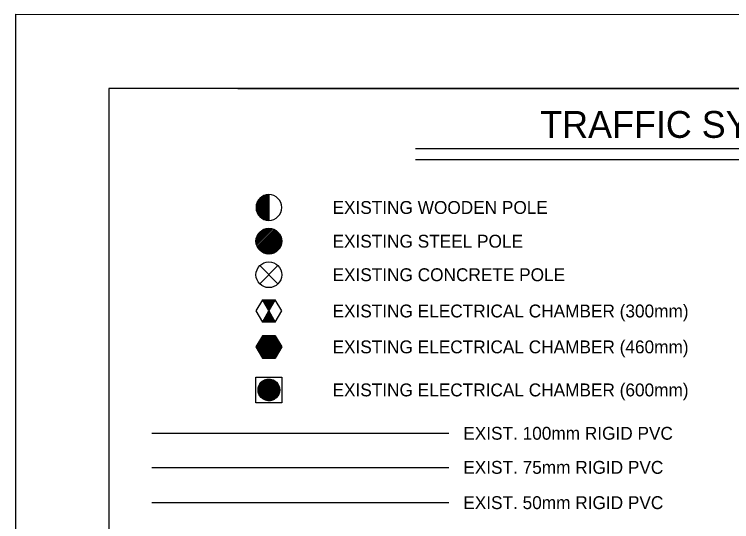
# Model space of a CAD drawing. Extents: x 595568 to 603392, y 4837996 to 4846579.
# Drawn here: x 603056.6 to 603080.76, y 4846519.3 to 4846536.38 of the extents above; entities that cross this region are included whole.
import ezdxf

# ---------------------------------------------------------------- set-up
doc = ezdxf.new("R2010")
doc.units = 0
for name, color, linetype in [('-PRINT HALFSIZE', 7, 'Continuous'), ('ENG_BORDER', 7, 'Continuous'), ('TCS_100mm-EXIST', 7, 'Continuous'), ('TCS_50mm-EXIST', 7, 'Continuous'), ('TCS_75mm-EXIST', 7, 'Continuous'), ('TCS_ELEC-CHAMBER-EXIST', 7, 'Continuous'), ('TCS_LEGEND', 7, 'Continuous'), ('TCS_POLE-EXIST', 7, 'Continuous')]:
    doc.layers.add(name, color=color, linetype=linetype)

msp = doc.modelspace()

# ---------------------------------------------------------------- linework, layer by layer
at = {"layer": '-PRINT HALFSIZE'}
msp.add_lwpolyline([(603056.659, 4846536.385), (603261.877, 4846536.304), (603261.821, 4846396.201), (603056.604, 4846396.282)], close=True, dxfattribs=at)
at = {"layer": 'ENG_BORDER'}
for points in [[(603258.618, 4846533.885), (603059.791, 4846533.885)], [(603059.791, 4846533.885), (603059.791, 4846399.391)]]:
    msp.add_lwpolyline(points, dxfattribs=at)
at = {"layer": 'TCS_100mm-EXIST'}
msp.add_line((603061.232, 4846522.272), (603071.232, 4846522.272), dxfattribs=at)
at = {"layer": 'TCS_50mm-EXIST'}
msp.add_line((603061.232, 4846519.936), (603071.232, 4846519.936), dxfattribs=at)
at = {"layer": 'TCS_75mm-EXIST'}
msp.add_line((603061.232, 4846521.124), (603071.232, 4846521.124), dxfattribs=at)
at = {"layer": 'TCS_ELEC-CHAMBER-EXIST'}
for p, q in [((603064.963, 4846526.758), (603064.972, 4846526.767)), ((603064.971, 4846526.745), (603064.993, 4846526.767)), ((603064.978, 4846526.732), (603065.013, 4846526.767)), ((603064.986, 4846526.719), (603065.033, 4846526.767)), ((603064.993, 4846526.706), (603065.054, 4846526.767)), ((603065.001, 4846526.693), (603065.074, 4846526.767)), ((603065.008, 4846526.68), (603065.095, 4846526.767)), ((603065.016, 4846526.668), (603065.115, 4846526.767)), ((603065.023, 4846526.655), (603065.136, 4846526.767)), ((603065.031, 4846526.642), (603065.156, 4846526.767)), ((603065.038, 4846526.629), (603065.177, 4846526.767)), ((603065.045, 4846526.616), (603065.197, 4846526.767)), ((603065.053, 4846526.603), (603065.217, 4846526.767)), ((603065.06, 4846526.59), (603065.238, 4846526.767)), ((603065.068, 4846526.577), (603065.258, 4846526.767)), ((603065.075, 4846526.564), (603065.279, 4846526.767)), ((603065.083, 4846526.551), (603065.299, 4846526.767)), ((603065.09, 4846526.538), (603065.32, 4846526.767)), ((603065.098, 4846526.525), (603065.34, 4846526.767)), ((603065.105, 4846526.512), (603065.361, 4846526.767)), ((603065.113, 4846526.499), (603065.381, 4846526.767)), ((603065.12, 4846526.486), (603065.378, 4846526.744)), ((603065.128, 4846526.473), (603065.35, 4846526.696)), ((603065.135, 4846526.46), (603065.323, 4846526.647)), ((603065.143, 4846526.447), (603065.295, 4846526.599)), ((603065.15, 4846526.434), (603065.267, 4846526.551)), ((603065.158, 4846526.421), (603065.239, 4846526.502)), ((603064.961, 4846526.016), (603065.234, 4846526.289)), ((603064.981, 4846526.016), (603065.242, 4846526.276)), ((603064.982, 4846526.057), (603065.227, 4846526.302)), ((603065.002, 4846526.016), (603065.249, 4846526.263)), ((603065.01, 4846526.106), (603065.219, 4846526.315)), ((603065.022, 4846526.016), (603065.257, 4846526.25)), ((603065.038, 4846526.154), (603065.212, 4846526.328)), ((603065.043, 4846526.016), (603065.264, 4846526.237)), ((603065.063, 4846526.016), (603065.271, 4846526.224)), ((603065.066, 4846526.202), (603065.204, 4846526.341)), ((603065.094, 4846526.251), (603065.197, 4846526.354)), ((603065.122, 4846526.299), (603065.189, 4846526.367)), ((603065.149, 4846526.348), (603065.182, 4846526.38)), ((603065.165, 4846526.408), (603065.211, 4846526.454)), ((603065.173, 4846526.395), (603065.183, 4846526.405)), ((603065.084, 4846526.016), (603065.279, 4846526.211)), ((603065.104, 4846526.016), (603065.286, 4846526.198)), ((603065.125, 4846526.016), (603065.294, 4846526.185)), ((603065.145, 4846526.016), (603065.301, 4846526.172)), ((603065.165, 4846526.016), (603065.309, 4846526.159)), ((603065.186, 4846526.016), (603065.316, 4846526.146)), ((603065.206, 4846526.016), (603065.324, 4846526.134)), ((603065.227, 4846526.016), (603065.331, 4846526.121)), ((603065.247, 4846526.016), (603065.339, 4846526.108)), ((603065.268, 4846526.016), (603065.346, 4846526.095)), ((603065.288, 4846526.016), (603065.354, 4846526.082)), ((603065.309, 4846526.016), (603065.361, 4846526.069)), ((603065.329, 4846526.016), (603065.369, 4846526.056)), ((603065.349, 4846526.016), (603065.376, 4846526.043)), ((603065.37, 4846526.016), (603065.384, 4846526.03)), ((603065.39, 4846526.016), (603065.391, 4846526.017)), ((603064.958, 4846525.559), (603064.741, 4846525.183)), ((603064.958, 4846525.559), (603064.741, 4846525.183)), ((603064.958, 4846525.559), (603064.741, 4846525.183)), ((603064.958, 4846525.559), (603064.741, 4846525.183)), ((603064.744, 4846525.188), (603065.115, 4846525.559)), ((603064.748, 4846525.171), (603065.135, 4846525.559)), ((603064.755, 4846525.158), (603065.155, 4846525.559)), ((603064.763, 4846525.146), (603065.176, 4846525.559)), ((603064.77, 4846525.133), (603065.196, 4846525.559)), ((603064.772, 4846525.237), (603065.094, 4846525.559)), ((603064.778, 4846525.12), (603065.217, 4846525.559)), ((603064.785, 4846525.107), (603065.237, 4846525.559)), ((603064.793, 4846525.094), (603065.258, 4846525.559)), ((603064.8, 4846525.081), (603065.278, 4846525.559)), ((603064.8, 4846525.285), (603065.074, 4846525.559)), ((603064.808, 4846525.068), (603065.299, 4846525.559)), ((603064.815, 4846525.055), (603065.319, 4846525.559)), ((603064.823, 4846525.042), (603065.339, 4846525.559)), ((603064.828, 4846525.333), (603065.053, 4846525.559)), ((603064.83, 4846525.029), (603065.36, 4846525.559)), ((603064.838, 4846525.016), (603065.38, 4846525.559)), ((603064.845, 4846525.003), (603065.395, 4846525.553)), ((603064.853, 4846524.99), (603065.403, 4846525.54)), ((603064.856, 4846525.382), (603065.033, 4846525.559)), ((603064.86, 4846524.977), (603065.41, 4846525.527)), ((603064.868, 4846524.964), (603065.418, 4846525.514)), ((603064.875, 4846524.951), (603065.425, 4846525.501)), ((603064.884, 4846525.43), (603065.012, 4846525.559)), ((603064.912, 4846525.478), (603064.992, 4846525.559)), ((603064.94, 4846525.527), (603064.971, 4846525.559)), ((603064.958, 4846525.559), (603065.392, 4846525.559)), ((603065.392, 4846525.559), (603064.958, 4846525.559)), ((603065.392, 4846525.559), (603064.958, 4846525.559)), ((603065.392, 4846525.559), (603064.958, 4846525.559)), ((603065.392, 4846525.559), (603065.609, 4846525.183)), ((603065.609, 4846525.183), (603065.392, 4846525.559)), ((603065.609, 4846525.183), (603065.392, 4846525.559)), ((603065.609, 4846525.183), (603065.392, 4846525.559)), ((603064.883, 4846524.938), (603065.432, 4846525.488)), ((603064.89, 4846524.925), (603065.44, 4846525.475)), ((603064.897, 4846524.912), (603065.447, 4846525.462)), ((603064.905, 4846524.899), (603065.455, 4846525.449)), ((603064.912, 4846524.886), (603065.462, 4846525.436)), ((603064.92, 4846524.873), (603065.47, 4846525.423)), ((603064.927, 4846524.86), (603065.477, 4846525.41)), ((603064.935, 4846524.847), (603065.485, 4846525.397)), ((603064.942, 4846524.834), (603065.492, 4846525.384)), ((603064.95, 4846524.821), (603065.5, 4846525.371)), ((603064.957, 4846524.808), (603065.507, 4846525.358)), ((603064.977, 4846524.807), (603065.515, 4846525.345)), ((603064.997, 4846524.807), (603065.522, 4846525.333)), ((603065.018, 4846524.807), (603065.53, 4846525.32)), ((603065.038, 4846524.807), (603065.537, 4846525.307)), ((603065.059, 4846524.807), (603065.545, 4846525.294)), ((603065.079, 4846524.807), (603065.552, 4846525.281)), ((603065.099, 4846524.807), (603065.56, 4846525.268)), ((603065.12, 4846524.807), (603065.567, 4846525.255)), ((603064.741, 4846525.183), (603064.958, 4846524.807)), ((603064.741, 4846525.183), (603064.958, 4846524.807)), ((603064.741, 4846525.183), (603064.958, 4846524.807)), ((603064.741, 4846525.183), (603064.958, 4846524.807)), ((603065.14, 4846524.807), (603065.575, 4846525.242)), ((603065.161, 4846524.807), (603065.582, 4846525.229)), ((603065.181, 4846524.807), (603065.59, 4846525.216)), ((603065.202, 4846524.807), (603065.597, 4846525.203)), ((603065.222, 4846524.807), (603065.605, 4846525.19)), ((603065.243, 4846524.807), (603065.596, 4846525.16)), ((603065.263, 4846524.807), (603065.568, 4846525.112)), ((603065.283, 4846524.807), (603065.54, 4846525.064)), ((603065.304, 4846524.807), (603065.512, 4846525.015)), ((603065.609, 4846525.183), (603065.392, 4846524.807)), ((603065.392, 4846524.807), (603065.609, 4846525.183)), ((603065.392, 4846524.807), (603065.609, 4846525.183)), ((603065.392, 4846524.807), (603065.609, 4846525.183)), ((603064.958, 4846524.807), (603065.392, 4846524.807)), ((603064.958, 4846524.807), (603065.392, 4846524.807)), ((603064.958, 4846524.807), (603065.392, 4846524.807)), ((603064.958, 4846524.807), (603065.392, 4846524.807)), ((603065.324, 4846524.807), (603065.484, 4846524.967)), ((603065.345, 4846524.807), (603065.456, 4846524.919)), ((603065.365, 4846524.807), (603065.428, 4846524.87)), ((603065.386, 4846524.807), (603065.4, 4846524.822)), ((603064.741, 4846524.167), (603065.609, 4846524.167)), ((603064.741, 4846523.299), (603064.741, 4846524.167)), ((603064.811, 4846523.723), (603065.185, 4846524.097)), ((603064.811, 4846523.733), (603065.174, 4846524.097)), ((603064.811, 4846523.744), (603065.164, 4846524.097)), ((603064.811, 4846523.713), (603065.194, 4846524.096)), ((603064.811, 4846523.754), (603065.153, 4846524.096)), ((603064.812, 4846523.704), (603065.204, 4846524.096)), ((603064.812, 4846523.765), (603065.142, 4846524.095)), ((603064.813, 4846523.694), (603065.213, 4846524.095)), ((603064.814, 4846523.685), (603065.222, 4846524.094)), ((603064.814, 4846523.777), (603065.131, 4846524.094)), ((603064.815, 4846523.676), (603065.231, 4846524.093)), ((603064.815, 4846523.789), (603065.119, 4846524.093)), ((603064.817, 4846523.668), (603065.24, 4846524.091)), ((603064.817, 4846523.801), (603065.107, 4846524.09)), ((603064.818, 4846523.659), (603065.249, 4846524.089)), ((603064.82, 4846523.651), (603065.257, 4846524.088)), ((603064.82, 4846523.814), (603065.094, 4846524.088)), ((603064.822, 4846523.642), (603065.265, 4846524.086)), ((603064.823, 4846523.828), (603065.08, 4846524.084)), ((603064.824, 4846523.634), (603065.273, 4846524.083)), ((603064.827, 4846523.627), (603065.281, 4846524.081)), ((603064.828, 4846523.842), (603065.066, 4846524.08)), ((603064.829, 4846523.619), (603065.289, 4846524.079)), ((603064.832, 4846523.611), (603065.297, 4846524.076)), ((603064.833, 4846523.858), (603065.05, 4846524.075)), ((603064.834, 4846523.604), (603065.304, 4846524.073)), ((603064.837, 4846523.596), (603065.311, 4846524.07)), ((603064.84, 4846523.874), (603065.033, 4846524.068)), ((603064.84, 4846523.589), (603065.319, 4846524.067)), ((603064.844, 4846523.582), (603065.326, 4846524.064)), ((603064.847, 4846523.575), (603065.333, 4846524.061)), ((603064.848, 4846523.893), (603065.014, 4846524.06)), ((603064.85, 4846523.568), (603065.34, 4846524.058)), ((603064.854, 4846523.561), (603065.346, 4846524.054)), ((603064.857, 4846523.555), (603065.353, 4846524.051)), ((603064.86, 4846523.915), (603064.993, 4846524.048)), ((603064.861, 4846523.548), (603065.359, 4846524.047)), ((603065.609, 4846524.167), (603065.609, 4846523.299)), ((603064.865, 4846523.542), (603065.366, 4846524.043)), ((603064.869, 4846523.536), (603065.372, 4846524.039)), ((603064.873, 4846523.53), (603065.378, 4846524.035)), ((603064.877, 4846523.523), (603065.384, 4846524.031)), ((603064.878, 4846523.944), (603064.964, 4846524.029)), ((603064.881, 4846523.518), (603065.39, 4846524.026)), ((603064.886, 4846523.512), (603065.396, 4846524.022)), ((603064.89, 4846523.506), (603065.402, 4846524.018)), ((603064.895, 4846523.5), (603065.407, 4846524.013)), ((603064.899, 4846523.495), (603065.413, 4846524.008)), ((603064.904, 4846523.489), (603065.418, 4846524.004)), ((603064.909, 4846523.484), (603065.424, 4846523.999)), ((603064.914, 4846523.479), (603065.429, 4846523.994)), ((603064.919, 4846523.474), (603065.434, 4846523.989)), ((603064.924, 4846523.469), (603065.439, 4846523.983)), ((603064.93, 4846523.464), (603065.444, 4846523.978)), ((603064.935, 4846523.459), (603065.449, 4846523.973)), ((603064.941, 4846523.454), (603065.454, 4846523.967)), ((603064.946, 4846523.449), (603065.458, 4846523.962)), ((603064.952, 4846523.445), (603065.463, 4846523.956)), ((603064.958, 4846523.441), (603065.467, 4846523.95)), ((603064.964, 4846523.436), (603065.471, 4846523.944)), ((603064.97, 4846523.432), (603065.476, 4846523.938)), ((603064.976, 4846523.428), (603065.48, 4846523.932)), ((603064.982, 4846523.424), (603065.484, 4846523.926)), ((603064.988, 4846523.42), (603065.488, 4846523.919)), ((603064.995, 4846523.416), (603065.491, 4846523.913)), ((603065.001, 4846523.413), (603065.495, 4846523.906)), ((603065.008, 4846523.409), (603065.499, 4846523.9)), ((603065.015, 4846523.406), (603065.502, 4846523.893)), ((603065.022, 4846523.402), (603065.505, 4846523.886)), ((603065.029, 4846523.399), (603065.509, 4846523.879)), ((603065.036, 4846523.396), (603065.512, 4846523.872)), ((603065.043, 4846523.393), (603065.514, 4846523.864)), ((603065.051, 4846523.39), (603065.517, 4846523.857)), ((603065.058, 4846523.388), (603065.52, 4846523.849)), ((603065.066, 4846523.385), (603065.522, 4846523.842)), ((603065.074, 4846523.383), (603065.525, 4846523.834)), ((603065.082, 4846523.381), (603065.527, 4846523.826)), ((603065.09, 4846523.379), (603065.529, 4846523.818)), ((603065.098, 4846523.377), (603065.531, 4846523.809)), ((603065.107, 4846523.375), (603065.533, 4846523.801)), ((603065.116, 4846523.374), (603065.534, 4846523.792)), ((603065.124, 4846523.372), (603065.536, 4846523.783)), ((603065.133, 4846523.371), (603065.537, 4846523.774)), ((603065.143, 4846523.37), (603065.538, 4846523.765)), ((603065.152, 4846523.369), (603065.538, 4846523.756)), ((603065.162, 4846523.369), (603065.539, 4846523.746)), ((603065.172, 4846523.369), (603065.539, 4846523.736)), ((603065.182, 4846523.369), (603065.539, 4846523.725)), ((603065.193, 4846523.369), (603065.539, 4846523.715)), ((603065.204, 4846523.37), (603065.538, 4846523.704)), ((603065.215, 4846523.371), (603065.537, 4846523.693)), ((603065.227, 4846523.372), (603065.535, 4846523.681)), ((603065.239, 4846523.374), (603065.533, 4846523.669)), ((603065.252, 4846523.377), (603065.531, 4846523.656)), ((603065.265, 4846523.38), (603065.528, 4846523.643)), ((603065.279, 4846523.384), (603065.524, 4846523.629)), ((603065.294, 4846523.389), (603065.519, 4846523.613)), ((603065.311, 4846523.395), (603065.513, 4846523.597)), ((603065.329, 4846523.403), (603065.505, 4846523.579)), ((603065.349, 4846523.413), (603065.495, 4846523.558)), ((603065.375, 4846523.428), (603065.479, 4846523.533)), ((603065.418, 4846523.461), (603065.447, 4846523.49)), ((603065.609, 4846523.299), (603064.741, 4846523.299))]:
    msp.add_line(p, q, dxfattribs=at)
for points in [[(603064.958, 4846526.767), (603064.741, 4846526.392), (603064.958, 4846526.016)], [(603065.392, 4846526.016), (603065.609, 4846526.392), (603065.392, 4846526.767)]]:
    msp.add_lwpolyline(points, dxfattribs=at)
for points in [[(603065.392, 4846526.767), (603065.175, 4846526.392), (603064.958, 4846526.767)], [(603064.958, 4846526.016), (603065.175, 4846526.392), (603065.392, 4846526.016)]]:
    msp.add_lwpolyline(points, close=True, dxfattribs=at)
msp.add_circle((603065.175, 4846523.733), 0.364, dxfattribs=at)
at = {"layer": 'TCS_LEGEND'}
for p, q in [((603070.116, 4846531.862), (603093.137, 4846531.862)), ((603070.116, 4846531.499), (603093.137, 4846531.499))]:
    msp.add_line(p, q, dxfattribs=at)
msp.add_lwpolyline([(603064.132, 4846533.885), (603099.121, 4846533.885)], dxfattribs=at)
at = {"layer": 'TCS_POLE-EXIST'}
for p, q in [((603064.742, 4846529.881), (603065.174, 4846530.312)), ((603064.743, 4846529.902), (603065.153, 4846530.312)), ((603064.743, 4846529.861), (603065.176, 4846530.294)), ((603064.744, 4846529.842), (603065.176, 4846530.274)), ((603064.745, 4846529.924), (603065.13, 4846530.31)), ((603064.746, 4846529.823), (603065.176, 4846530.253)), ((603064.748, 4846529.948), (603065.107, 4846530.307)), ((603064.748, 4846529.805), (603065.176, 4846530.233)), ((603064.752, 4846529.788), (603065.176, 4846530.212)), ((603064.753, 4846529.973), (603065.081, 4846530.302)), ((603064.756, 4846529.772), (603065.176, 4846530.192)), ((603064.76, 4846530.001), (603065.054, 4846530.295)), ((603064.76, 4846529.756), (603065.176, 4846530.171)), ((603064.765, 4846529.74), (603065.176, 4846530.151)), ((603064.77, 4846530.032), (603065.023, 4846530.285)), ((603064.77, 4846529.725), (603065.176, 4846530.131)), ((603064.776, 4846529.71), (603065.176, 4846530.11)), ((603064.782, 4846529.696), (603065.176, 4846530.09)), ((603064.785, 4846530.067), (603064.987, 4846530.269)), ((603064.812, 4846530.114), (603064.941, 4846530.243)), ((603065.176, 4846530.312), (603065.176, 4846529.445)), ((603065.176, 4846530.312), (603065.176, 4846530.312)), ((603064.789, 4846529.682), (603065.176, 4846530.069)), ((603064.796, 4846529.669), (603065.176, 4846530.049)), ((603064.804, 4846529.656), (603065.176, 4846530.028)), ((603064.812, 4846529.644), (603065.176, 4846530.008)), ((603064.82, 4846529.631), (603065.176, 4846529.987)), ((603064.828, 4846529.619), (603065.176, 4846529.967)), ((603064.837, 4846529.608), (603065.176, 4846529.947)), ((603064.846, 4846529.597), (603065.176, 4846529.926)), ((603064.856, 4846529.586), (603065.176, 4846529.906)), ((603064.866, 4846529.575), (603065.176, 4846529.885)), ((603064.876, 4846529.565), (603065.176, 4846529.865)), ((603064.887, 4846529.555), (603065.176, 4846529.844)), ((603064.898, 4846529.546), (603065.176, 4846529.824)), ((603064.909, 4846529.537), (603065.176, 4846529.803)), ((603064.921, 4846529.528), (603065.176, 4846529.783)), ((603064.933, 4846529.519), (603065.176, 4846529.762)), ((603064.945, 4846529.511), (603065.176, 4846529.742)), ((603064.958, 4846529.504), (603065.176, 4846529.722)), ((603064.971, 4846529.496), (603065.176, 4846529.701)), ((603064.985, 4846529.489), (603065.176, 4846529.681)), ((603064.998, 4846529.483), (603065.176, 4846529.66)), ((603065.013, 4846529.477), (603065.176, 4846529.64)), ((603065.028, 4846529.471), (603065.176, 4846529.619)), ((603065.043, 4846529.466), (603065.176, 4846529.599)), ((603065.058, 4846529.461), (603065.176, 4846529.578)), ((603065.075, 4846529.457), (603065.176, 4846529.558)), ((603065.091, 4846529.453), (603065.176, 4846529.538)), ((603065.109, 4846529.45), (603065.176, 4846529.517)), ((603065.127, 4846529.448), (603065.176, 4846529.497)), ((603065.146, 4846529.446), (603065.176, 4846529.476)), ((603065.165, 4846529.445), (603065.176, 4846529.456)), ((603065.175, 4846529.445), (603065.176, 4846529.446)), ((603064.741, 4846528.737), (603065.181, 4846529.177)), ((603064.744, 4846528.791), (603065.127, 4846529.174)), ((603064.744, 4846528.689), (603065.229, 4846529.173)), ((603064.752, 4846528.646), (603065.272, 4846529.166)), ((603064.755, 4846528.854), (603065.064, 4846529.162)), ((603064.763, 4846528.606), (603065.312, 4846529.155)), ((603064.778, 4846528.569), (603065.349, 4846529.14)), ((603064.786, 4846528.935), (603064.983, 4846529.132)), ((603064.794, 4846528.535), (603065.383, 4846529.124)), ((603064.814, 4846528.503), (603065.415, 4846529.104)), ((603064.835, 4846528.473), (603065.445, 4846529.083)), ((603064.859, 4846528.446), (603065.472, 4846529.059)), ((603064.885, 4846528.421), (603065.497, 4846529.033)), ((603064.913, 4846528.397), (603065.52, 4846529.005)), ((603064.943, 4846528.377), (603065.541, 4846528.975)), ((603064.975, 4846528.358), (603065.56, 4846528.943)), ((603065.01, 4846528.342), (603065.576, 4846528.908)), ((603065.048, 4846528.328), (603065.59, 4846528.87)), ((603065.089, 4846528.318), (603065.6, 4846528.829)), ((603065.133, 4846528.311), (603065.607, 4846528.785)), ((603065.182, 4846528.309), (603065.609, 4846528.735)), ((603065.238, 4846528.314), (603065.604, 4846528.68)), ((603065.304, 4846528.329), (603065.589, 4846528.614)), ((603065.397, 4846528.37), (603065.548, 4846528.521)), ((603064.868, 4846527.92), (603065.482, 4846527.307)), ((603064.868, 4846527.307), (603065.482, 4846527.92))]:
    msp.add_line(p, q, dxfattribs=at)
for centre in [(603065.175, 4846528.743), (603065.175, 4846527.613)]:
    msp.add_circle(centre, 0.434, dxfattribs=at)
for centre, start, end in [((603065.176, 4846529.879), 90, 270), ((603065.174, 4846529.879), 270, 90)]:
    msp.add_arc(centre, 0.434, start, end, dxfattribs=at)

# ---------------------------------------------------------------- texts
at = {"layer": 'TCS_LEGEND'}
for s, height, p in [('TRAFFIC SYMBOLS LEGEND', 0.90363, (603074.313, 4846532.224)), ('EXISTING WOODEN POLE', 0.43374, (603067.318, 4846529.662)), ('EXISTING STEEL POLE', 0.43374, (603067.318, 4846528.526)), ('EXISTING CONCRETE POLE', 0.43374, (603067.318, 4846527.397)), ('EXISTING ELECTRICAL CHAMBER (300mm)', 0.43374, (603067.318, 4846526.175)), ('EXISTING ELECTRICAL CHAMBER (460mm)', 0.43374, (603067.318, 4846524.966)), ('EXISTING ELECTRICAL CHAMBER (600mm)', 0.43374, (603067.318, 4846523.516)), ('EXIST. 100mm RIGID PVC', 0.43374, (603071.721, 4846522.056)), ('EXIST. 75mm RIGID PVC', 0.43374, (603071.721, 4846520.908)), ('EXIST. 50mm RIGID PVC', 0.43374, (603071.721, 4846519.719))]:
    msp.add_text(s, height=height, dxfattribs=at).set_placement(p)

doc.saveas('drawing.dxf')
